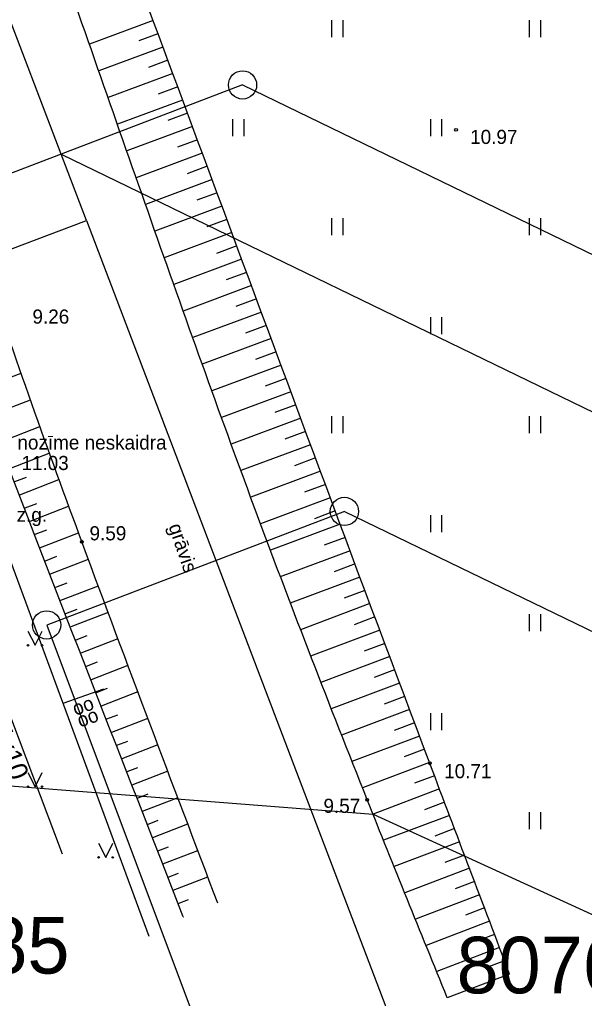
# Model space of a CAD drawing. Extents: x 503353 to 504004, y 304662 to 305049.
# Drawn here: x 503404.45 to 503424.44, y 304952.51 to 304987.12 of the extents above; entities that cross this region are included whole.
import ezdxf

# ---------------------------------------------------------------- set-up
doc = ezdxf.new("R2010")
doc.units = 0
for name, color, linetype in [('25', 7, 'Continuous'), ('59', 7, 'Continuous'), ('APGR_ELEM_####_####_#', 7, 'Continuous'), ('APGR_SARK_####_####_#', 7, 'Continuous'), ('APGS_VADP_ZSPR_####_#', 7, 'Continuous'), ('APGS_VADP_ZSPR_TKST_#', 7, 'Continuous'), ('HIDG_GRAV_####_TKST_#', 7, 'Continuous'), ('HIDG_PLIN_####_####_#', 7, 'Continuous'), ('LKAN_ELEM_PAST_TKST_#', 7, 'Continuous'), ('RAMI_UZMR_####_####_#', 7, 'Continuous'), ('RELJ_AATZ_####_TKST_#', 7, 'Continuous'), ('RELJ_ELEM_####_####_#', 7, 'Continuous'), ('RELJ_NOGA_####_####_#', 7, 'Continuous'), ('SAKK_ELEM_####_TKST_#', 7, 'Continuous'), ('SAKK_IZVK_####_TKST_#', 7, 'Continuous'), ('SAKK_KKAN_####_####_#', 7, 'Continuous'), ('TERT_ELEM_####_####_#', 7, 'Continuous')]:
    doc.layers.add(name, color=color, linetype=linetype)

msp = doc.modelspace()

# ---------------------------------------------------------------- linework, layer by layer
at = {"layer": '25'}
for p, q in [((503405.924, 304982.367), (503395.906, 305008.647)), ((503406.819, 304980.02), (503405.924, 304982.367)), ((503405.924, 304982.367), (503425.185, 304973.036)), ((503401.316, 304977.953), (503406.819, 304980.02)), ((503406.819, 304980.02), (503423.697, 304935.749))]:
    msp.add_line(p, q, dxfattribs=at)
at = {"layer": 'APGR_ELEM_####_####_#'}
for p, q in [((503412.342, 304984.814), (503400.006, 304980.111)), ((503412.342, 304984.814), (503586.697, 304900.345)), ((503415.949, 304969.732), (503405.413, 304965.716)), ((503415.949, 304969.732), (503588.684, 304886.049))]:
    msp.add_line(p, q, dxfattribs=at)
for centre in [(503412.342, 304984.814), (503415.949, 304969.732), (503405.41, 304965.72)]:
    msp.add_circle(centre, 0.5, dxfattribs=at)
at = {"layer": 'APGR_SARK_####_####_#'}
msp.add_line((503405.413, 304965.716), (503412.468, 304946.934), dxfattribs=at)
at = {"layer": 'APGS_VADP_ZSPR_####_#'}
msp.add_line((503405.972, 304957.61), (503401.476, 304969.504), dxfattribs=at)
at = {"layer": 'HIDG_PLIN_####_####_#'}
for points in [[(503419.587, 304952.537), (503416.755, 304959.536), (503412.876, 304969.575), (503409.221, 304979.701), (503405.654, 304989.86), (503402.036, 305000), (503392.74, 305025.488)], [(503411.469, 304955.877), (503406.678, 304968.605), (503404.887, 304973.537), (503403.172, 304978.498), (503401.476, 304983.466), (503399.743, 304988.42), (503397.13, 304995.726), (503394.508, 305003.029), (503389.116, 305017.581), (503386.254, 305025.055)]]:
    msp.add_spline(points, degree=3, dxfattribs=at)
at = {"layer": 'RAMI_UZMR_####_####_#'}
msp.add_lwpolyline([(503407.219, 305023.925), (503368.776, 305020.183), (503379.431, 304977.462), (503383.452, 304957.421), (503396.867, 304960.598), (503416.959, 304959.032), (503433.698, 304951.36), (503608.791, 304871.751), (503642.724, 304858.177), (503694.651, 304834.724), (503842.283, 304765.867)], dxfattribs=at)
at = {"layer": 'RELJ_ELEM_####_####_#'}
for centre in [(503419.897, 304983.226), (503406.656, 304968.662), (503418.967, 304960.829), (503416.755, 304959.536)]:
    msp.add_circle(centre, 0.05, dxfattribs=at)
at = {"layer": 'RELJ_NOGA_####_####_#'}
for p, q in [((503409.176, 304987.091), (503406.923, 304986.255)), ((503409.35, 304986.623), (503408.672, 304986.371)), ((503409.524, 304986.154), (503407.253, 304985.311)), ((503409.698, 304985.685), (503409.014, 304985.431)), ((503409.872, 304985.217), (503407.584, 304984.366)), ((503410.047, 304984.748), (503409.357, 304984.492)), ((503410.221, 304984.279), (503407.914, 304983.422)), ((503410.395, 304983.81), (503409.7, 304983.552)), ((503410.569, 304983.342), (503408.245, 304982.478)), ((503410.743, 304982.873), (503410.043, 304982.613)), ((503410.917, 304982.404), (503408.576, 304981.534)), ((503411.091, 304981.936), (503410.386, 304981.674)), ((503411.266, 304981.467), (503408.908, 304980.591)), ((503411.44, 304980.998), (503410.73, 304980.735)), ((503411.614, 304980.53), (503409.24, 304979.648)), ((503411.788, 304980.061), (503411.074, 304979.795)), ((503411.962, 304979.592), (503409.574, 304978.704)), ((503412.137, 304979.124), (503411.418, 304978.856)), ((503412.311, 304978.655), (503409.908, 304977.762)), ((503412.485, 304978.186), (503411.762, 304977.918)), ((503412.659, 304977.718), (503410.244, 304976.82)), ((503412.834, 304977.249), (503412.107, 304976.979)), ((503413.008, 304976.78), (503410.581, 304975.878)), ((503413.182, 304976.312), (503412.452, 304976.04)), ((503413.356, 304975.843), (503410.919, 304974.937)), ((503413.531, 304975.374), (503412.798, 304975.102)), ((503413.705, 304974.906), (503411.259, 304973.996)), ((503403.021, 304974.052), (503404.506, 304974.628)), ((503413.879, 304974.437), (503413.144, 304974.164)), ((503403.382, 304973.12), (503404.836, 304973.683)), ((503414.053, 304973.968), (503411.6, 304973.056)), ((503414.228, 304973.5), (503413.491, 304973.226)), ((503414.402, 304973.031), (503411.942, 304972.116)), ((503403.743, 304972.188), (503405.168, 304972.74)), ((503414.576, 304972.563), (503413.838, 304972.287)), ((503414.751, 304972.094), (503412.286, 304971.176)), ((503404.105, 304971.255), (503405.504, 304971.797)), ((503414.925, 304971.625), (503414.185, 304971.35)), ((503404.285, 304970.789), (503404.702, 304970.95)), ((503415.1, 304971.157), (503412.631, 304970.238)), ((503404.466, 304970.323), (503405.844, 304970.857)), ((503415.274, 304970.688), (503414.533, 304970.412)), ((503415.449, 304970.22), (503412.979, 304969.298)), ((503404.647, 304969.856), (503405.058, 304970.016)), ((503404.827, 304969.39), (503406.189, 304969.918)), ((503415.624, 304969.751), (503414.883, 304969.475)), ((503415.799, 304969.283), (503413.327, 304968.361)), ((503405.008, 304968.924), (503405.414, 304969.081)), ((503405.189, 304968.458), (503406.537, 304968.98)), ((503415.974, 304968.815), (503415.232, 304968.538)), ((503405.369, 304967.992), (503405.773, 304968.148)), ((503416.148, 304968.346), (503413.679, 304967.424)), ((503405.55, 304967.525), (503406.889, 304968.044)), ((503416.323, 304967.878), (503415.583, 304967.601)), ((503405.731, 304967.059), (503406.131, 304967.214)), ((503405.911, 304966.593), (503407.241, 304967.108)), ((503416.498, 304967.409), (503414.032, 304966.489)), ((503416.673, 304966.941), (503415.934, 304966.664)), ((503416.848, 304966.473), (503414.389, 304965.552)), ((503406.092, 304966.127), (503406.49, 304966.281)), ((503406.273, 304965.661), (503407.594, 304966.172)), ((503417.024, 304966.004), (503416.287, 304965.729)), ((503406.453, 304965.194), (503406.848, 304965.347)), ((503417.199, 304965.536), (503414.748, 304964.619)), ((503406.634, 304964.728), (503407.946, 304965.236)), ((503417.374, 304965.068), (503416.641, 304964.793)), ((503406.815, 304964.262), (503407.207, 304964.414)), ((503406.995, 304963.796), (503408.298, 304964.301)), ((503417.55, 304964.6), (503415.11, 304963.684)), ((503417.725, 304964.131), (503416.995, 304963.858)), ((503417.901, 304963.663), (503415.474, 304962.753)), ((503407.176, 304963.329), (503407.566, 304963.48)), ((503407.357, 304962.863), (503408.651, 304963.365)), ((503418.077, 304963.195), (503417.351, 304962.922)), ((503418.253, 304962.727), (503415.842, 304961.82)), ((503407.537, 304962.397), (503407.924, 304962.547)), ((503407.718, 304961.931), (503409.003, 304962.429)), ((503418.429, 304962.259), (503417.708, 304961.988)), ((503407.899, 304961.465), (503408.283, 304961.613)), ((503418.605, 304961.791), (503416.211, 304960.89)), ((503408.079, 304960.998), (503409.355, 304961.493)), ((503418.781, 304961.323), (503418.066, 304961.054)), ((503418.957, 304960.855), (503416.583, 304959.962)), ((503408.26, 304960.532), (503408.642, 304960.68)), ((503408.441, 304960.066), (503409.708, 304960.557)), ((503419.134, 304960.388), (503418.425, 304960.12)), ((503419.31, 304959.92), (503416.959, 304959.032)), ((503408.621, 304959.6), (503409, 304959.746)), ((503408.802, 304959.133), (503410.06, 304959.621)), ((503419.487, 304959.452), (503418.785, 304959.187)), ((503408.983, 304958.667), (503409.359, 304958.813)), ((503419.664, 304958.984), (503417.334, 304958.104)), ((503409.163, 304958.201), (503410.412, 304958.685)), ((503419.841, 304958.517), (503419.146, 304958.253)), ((503409.344, 304957.735), (503409.717, 304957.879)), ((503409.525, 304957.269), (503410.765, 304957.749)), ((503420.018, 304958.049), (503417.71, 304957.175)), ((503420.195, 304957.582), (503419.506, 304957.321)), ((503420.373, 304957.114), (503418.086, 304956.248)), ((503409.705, 304956.802), (503410.076, 304956.946)), ((503409.886, 304956.336), (503411.117, 304956.813)), ((503420.55, 304956.647), (503419.867, 304956.387)), ((503410.067, 304955.87), (503410.435, 304956.012)), ((503420.728, 304956.179), (503418.461, 304955.319)), ((503420.905, 304955.712), (503420.228, 304955.455)), ((503410.247, 304955.404), (503410.248, 304955.404)), ((503421.083, 304955.244), (503418.837, 304954.391)), ((503421.26, 304954.777), (503420.589, 304954.522)), ((503421.438, 304954.31), (503419.212, 304953.464)), ((503421.615, 304953.842), (503420.951, 304953.59)), ((503421.793, 304953.375), (503419.587, 304952.537))]:
    msp.add_line(p, q, dxfattribs=at)
for points in [[(503421.793, 304953.375), (503418.978, 304960.8), (503411.664, 304980.395), (503404.379, 305000), (503394.998, 305025.189)], [(503421.793, 304953.375), (503418.978, 304960.8), (503411.664, 304980.395), (503404.379, 305000), (503395.14, 305024.807)], [(503410.247, 304955.404), (503401.902, 304976.94), (503397.494, 304988.727), (503387.268, 305016.834), (503384.58, 305024.465)]]:
    msp.add_spline(points, degree=3, dxfattribs=at)
at = {"layer": 'SAKK_IZVK_####_TKST_#'}
msp.add_line((503407.422, 304963.448), (503405.986, 304962.94), dxfattribs=at)
at = {"layer": 'SAKK_KKAN_####_####_#'}
msp.add_line((503407.422, 304963.449), (503405.986, 304962.94), dxfattribs=at)
msp.add_lwpolyline([(503392.141, 305000), (503403.85, 304968.741), (503409.025, 304954.715)], dxfattribs=at)
at = {"layer": 'TERT_ELEM_####_####_#'}
for p, q in [((503415.5, 304986.5), (503415.5, 304987.1)), ((503415.9, 304986.5), (503415.9, 304987.1)), ((503422.5, 304986.5), (503422.5, 304987.1)), ((503422.9, 304986.5), (503422.9, 304987.1)), ((503412, 304983), (503412, 304983.6)), ((503412.4, 304983), (503412.4, 304983.6)), ((503419, 304983), (503419, 304983.6)), ((503419.4, 304983), (503419.4, 304983.6)), ((503415.5, 304979.5), (503415.5, 304980.1)), ((503415.9, 304979.5), (503415.9, 304980.1)), ((503422.5, 304979.5), (503422.5, 304980.1)), ((503422.9, 304979.5), (503422.9, 304980.1)), ((503419, 304976), (503419, 304976.6)), ((503419.4, 304976), (503419.4, 304976.6)), ((503415.5, 304972.5), (503415.5, 304973.1)), ((503415.9, 304972.5), (503415.9, 304973.1)), ((503422.5, 304972.5), (503422.5, 304973.1)), ((503422.9, 304972.5), (503422.9, 304973.1)), ((503419, 304969), (503419, 304969.6)), ((503419.4, 304969), (503419.4, 304969.6)), ((503422.5, 304965.5), (503422.5, 304966.1)), ((503422.9, 304965.5), (503422.9, 304966.1)), ((503404.75, 304965.5), (503405, 304965)), ((503405, 304965), (503405.25, 304965.5)), ((503419, 304962), (503419, 304962.6)), ((503419.4, 304962), (503419.4, 304962.6)), ((503404.75, 304960.5), (503405, 304960)), ((503405, 304960), (503405.25, 304960.5)), ((503422.5, 304958.5), (503422.5, 304959.1)), ((503422.9, 304958.5), (503422.9, 304959.1)), ((503407.25, 304958), (503407.5, 304957.5)), ((503407.5, 304957.5), (503407.75, 304958))]:
    msp.add_line(p, q, dxfattribs=at)
for centre, radius in [((503404.75, 304965), 0.028), ((503405.25, 304965), 0.0263), ((503404.75, 304960), 0.028), ((503405.25, 304960), 0.0263), ((503407.25, 304957.5), 0.028), ((503407.75, 304957.5), 0.0263)]:
    msp.add_circle(centre, radius, dxfattribs=at)

# ---------------------------------------------------------------- texts
at = {"layer": '59'}
for s, p in [('80760071585', (503389.856, 304953.393)), ('80760080266', (503419.918, 304952.694))]:
    msp.add_text(s, height=2, dxfattribs=at).set_placement(p)
at = {"layer": 'APGS_VADP_ZSPR_TKST_#'}
msp.add_text('MCMK 4x10', height=0.7, rotation=290.7078, dxfattribs=at).set_placement((503402.331, 304964.992))
at = {"layer": 'HIDG_GRAV_####_TKST_#'}
msp.add_text('grāvis', height=0.5, rotation=288.7993, dxfattribs=at).set_placement((503409.717, 304969.209))
at = {"layer": 'LKAN_ELEM_PAST_TKST_#'}
for s, p in [('nozīme neskaidra', (503404.376, 304971.922)), ('11.03', (503404.518, 304971.197))]:
    msp.add_text(s, height=0.5, dxfattribs=at).set_placement(p)
at = {"layer": 'RELJ_AATZ_####_TKST_#'}
for s, p in [('10.97', (503420.397, 304982.726)), (' 9.26', (503404.723, 304976.373)), ('9.59', (503406.928, 304968.711)), ('10.71', (503419.478, 304960.3)), ('9.57', (503415.206, 304959.075))]:
    msp.add_text(s, height=0.5, dxfattribs=at).set_placement(p)
at = {"layer": 'SAKK_ELEM_####_TKST_#'}
msp.add_text('z.g.', height=0.5, dxfattribs=at).set_placement((503404.348, 304969.366))
at = {"layer": 'SAKK_IZVK_####_TKST_#'}
for p in [(503406.429, 304962.506), (503406.594, 304962.088)]:
    msp.add_text('oo', height=0.5, rotation=19.5152, dxfattribs=at).set_placement(p)

doc.saveas('drawing.dxf')
